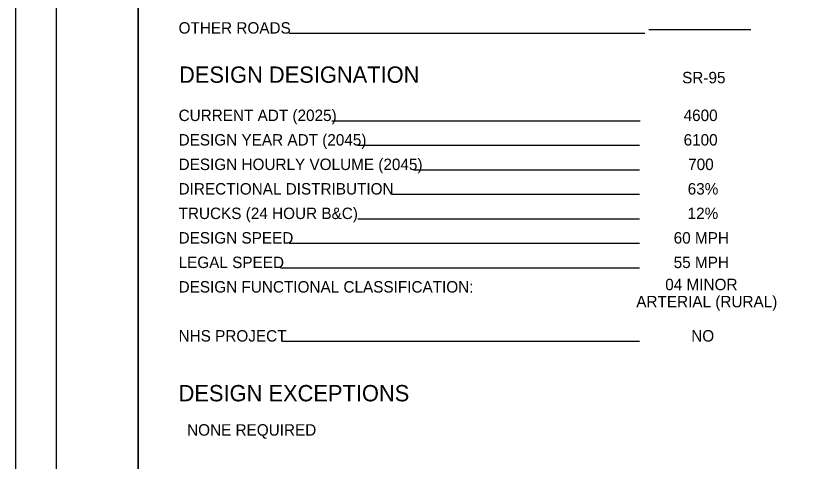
# Model space of a CAD drawing. Extents: x 0 to 34, y 0 to 22.
# Drawn here: x 0 to 9.58, y 5.64 to 11.1 of the extents above; entities that cross this region are included whole.
import ezdxf

# ---------------------------------------------------------------- set-up
doc = ezdxf.new("R2010")
doc.units = 0
for name, color, linetype in [('SH_Border', 7, 'Continuous'), ('SH_Cut_Line', 7, 'Continuous'), ('SH_Data', 7, 'Continuous'), ('SH_Text', 7, 'Continuous')]:
    doc.layers.add(name, color=color, linetype=linetype)

msp = doc.modelspace()

# ---------------------------------------------------------------- linework, layer by layer
at = {"layer": 'SH_Cut_Line'}
for p, q in [((9, 10.9223), (7.75, 10.9223)), ((7.7, 10.8767), (3.3471, 10.8767)), ((7.6424, 9.8062), (3.871, 9.8062)), ((7.6368, 9.5062), (4.1885, 9.5062)), ((7.6368, 9.2062), (4.8723, 9.2062)), ((7.6368, 8.9062), (4.6037, 8.9062)), ((7.6368, 8.6062), (4.1885, 8.6062)), ((7.6368, 8.3062), (3.346, 8.3062)), ((7.6368, 8.0062), (3.2422, 8.0062)), ((7.6368, 7.1062), (3.2669, 7.1062))]:
    msp.add_line(p, q, dxfattribs=at)
at = {"layer": 'SH_Data'}
for points in [[(0.5, 21.5), (1.5, 21.5), (1.5, 0.5), (0.5, 0.5)], [(1.5, 21.5), (33.5, 21.5), (33.5, 0.5), (1.5, 0.5)]]:
    msp.add_lwpolyline(points, close=True, dxfattribs=at)
at = {"layer": 'SH_Text'}
msp.add_lwpolyline([(0, 0), (34, 0), (34, 22), (0, 22)], close=True, dxfattribs=at)

# ---------------------------------------------------------------- texts
at = {"layer": 'SH_Border'}
for s, height, p in [('OTHER ROADS', 0.14, (1.9944, 10.8767)), ('SR-95', 0.14, (8.1578, 10.2684)), ('CURRENT ADT (2025)', 0.14, (1.9944, 9.8062)), ('4600', 0.14, (8.1758, 9.8062)), ('DESIGN YEAR ADT (2045)', 0.14, (1.9944, 9.5062)), ('6100', 0.14, (8.1758, 9.5062)), ('DESIGN HOURLY VOLUME (2045)', 0.14, (1.9944, 9.2062)), ('700', 0.14, (8.2317, 9.2062)), ('DIRECTIONAL DISTRIBUTION', 0.14, (1.9944, 8.9062)), ('63%', 0.14, (8.2258, 8.9062)), ('TRUCKS (24 HOUR B&C)', 0.14, (1.9944, 8.6062)), ('12%', 0.14, (8.2247, 8.6062)), ('DESIGN SPEED', 0.14, (1.9944, 8.3062)), ('60 MPH', 0.14, (8.0543, 8.3062)), ('LEGAL SPEED', 0.14, (1.9944, 8.0062)), ('55 MPH', 0.14, (8.0543, 8.0062)), ('04 MINOR ', 0.14, (7.9512, 7.7353)), ('DESIGN FUNCTIONAL CLASSIFICATION:', 0.14, (1.9944, 7.7062)), ('ARTERIAL (RURAL)', 0.14, (7.5962, 7.5253)), ('NHS PROJECT', 0.14, (1.9944, 7.1062)), ('NO', 0.14, (8.2695, 7.1062)), ('DESIGN EXCEPTIONS', 0.2, (1.9944, 6.3744)), ('  NONE REQUIRED                          ', 0.14, (1.9944, 5.9544))]:
    msp.add_text(s, height=height, dxfattribs=at).set_placement(p)
at = {"layer": 'SH_Cut_Line'}
msp.add_text('DESIGN DESIGNATION', height=0.2, dxfattribs=at).set_placement((2, 10.2747))

doc.saveas('drawing.dxf')
